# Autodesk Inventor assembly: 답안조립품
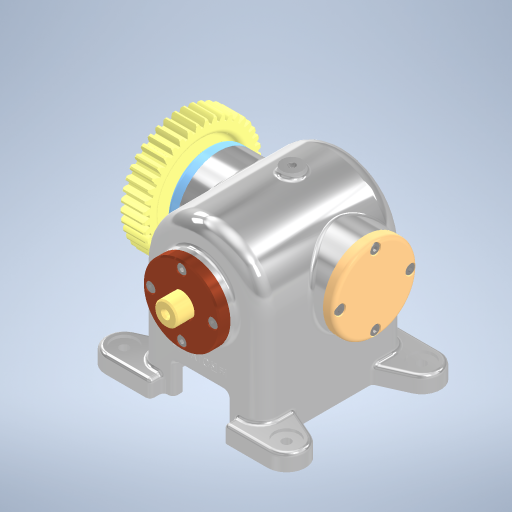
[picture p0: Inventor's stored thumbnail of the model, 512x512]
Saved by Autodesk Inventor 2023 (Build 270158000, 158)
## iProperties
Created: 2024-09
Part Number: 답안조립품
Document SubType Name: Assembly
Designer: asung
Author: asung
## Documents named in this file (12)
- C:\Users\asung\Desktop\740904V1009\답안조립품.iam
- C:\Users\asung\Desktop\740904V1009\본체.ipt
- C:\Users\asung\Desktop\740904V1009\740904V1009\뒷커버.ipt
- C:\Users\asung\Desktop\740904V1009\740904V1009\앞커버.ipt
- C:\Users\asung\Desktop\740904V1009\740904V1009\편심축.ipt
- C:\Users\asung\Desktop\740904V1009\740904V1009\깊은 홈 볼베어링 6203.ipt
- C:\Users\asung\Desktop\740904V1009\740904V1009\로드.ipt
- C:\Users\asung\Desktop\740904V1009\740904V1009\부시.ipt
- C:\Users\asung\Desktop\740904V1009\740904V1009\육각 소켓 머리 볼트 M4x10.ipt
- C:\Users\asung\Desktop\740904V1009\740904V1009\오일실 17 32 8.ipt
- C:\Users\asung\Desktop\740904V1009\740904V1009\스퍼 기어.ipt
- C:\Users\asung\Desktop\740904V1009\740904V1009\평행키 3x3x14.ipt
